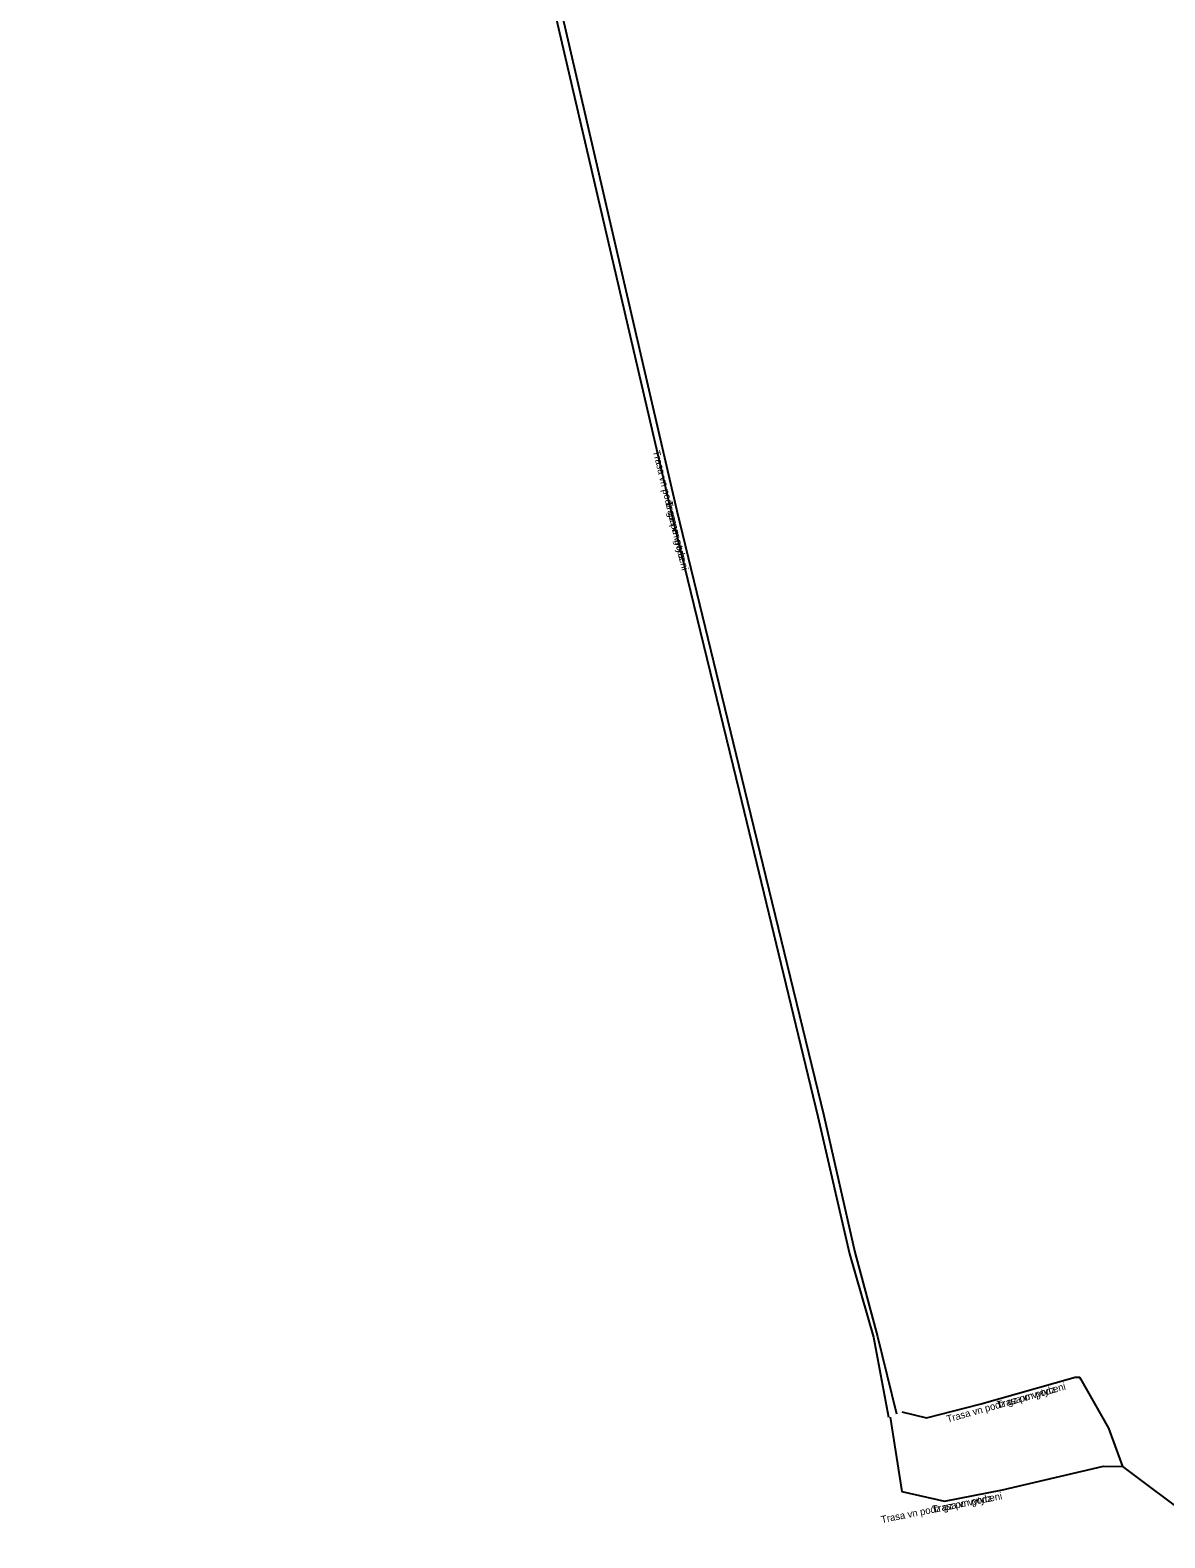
# Model space of a CAD drawing. Extents: x -473162 to -472629, y -1107202 to -1106680.
# Drawn here: x -472952.7 to -472873, y -1107033.1 to -1106927.1 of the extents above; entities that cross this region are included whole.
import ezdxf

# ---------------------------------------------------------------- set-up
doc = ezdxf.new("R2010")
doc.units = 0
doc.layers.add('Popiskový text - Ostatní atributy Trasy', color=7, linetype='Continuous')
doc.layers.add('Spojnice VN', color=7, linetype='Continuous')

msp = doc.modelspace()

# ---------------------------------------------------------------- linework, layer by layer
at = {"layer": 'Spojnice VN'}
for points in [[(-472959.07, -1106901.51), (-472948.71, -1106898.85), (-472943.76, -1106897.66), (-472940.88, -1106899.23), (-472933.49, -1106903.53), (-472927.53, -1106903.31), (-472922.71, -1106902.64), (-472919.35, -1106909.88), (-472918.15, -1106915.27), (-472916.55, -1106922.8), (-472907.68, -1106960.98), (-472902.89, -1106980.6), (-472897.36, -1107003.49), (-472895.13, -1107013.14), (-472893.44, -1107019.01), (-472892.38, -1107024.63)], [(-472959.07, -1106901.51), (-472948.71, -1106898.85), (-472943.76, -1106897.66), (-472940.88, -1106899.23), (-472933.49, -1106903.53), (-472927.53, -1106903.31), (-472922.71, -1106902.64), (-472919.35, -1106909.88), (-472918.15, -1106915.27), (-472916.55, -1106922.8), (-472907.68, -1106960.98), (-472902.89, -1106980.6), (-472897.36, -1107003.49), (-472895.13, -1107013.14), (-472893.44, -1107019.01), (-472892.38, -1107024.63)], [(-472922.47, -1106902.33), (-472919.06, -1106909.81), (-472917.89, -1106915.23), (-472916.11, -1106922.66), (-472907.28, -1106960.88), (-472902.51, -1106980.47), (-472896.93, -1107003.41), (-472894.77, -1107013.03), (-472893.17, -1107018.95), (-472891.83, -1107024.39)], [(-472922.47, -1106902.33), (-472919.06, -1106909.81), (-472917.89, -1106915.23), (-472916.11, -1106922.66), (-472907.28, -1106960.88), (-472902.51, -1106980.47), (-472896.93, -1107003.41), (-472894.77, -1107013.03), (-472893.17, -1107018.95), (-472891.83, -1107024.39)], [(-472875.93, -1107028.1), (-472871, -1107031.82), (-472861.33, -1107033.12), (-472850.8, -1107030.64), (-472845.32, -1107029.36), (-472833.57, -1107026.45), (-472822.85, -1107023.72), (-472815.1, -1107022.25), (-472801.34, -1107019), (-472791.51, -1107016.55), (-472781.55, -1107013.95), (-472772.18, -1107011.27), (-472769.48, -1107010.31), (-472760.41, -1107005.48), (-472750.82, -1106999.47), (-472737.83, -1106992.21), (-472734.32, -1106989.81), (-472728.85, -1106987.34), (-472726.78, -1106986.17), (-472724.29, -1106985.16)], [(-472875.93, -1107028.1), (-472871, -1107031.82), (-472861.33, -1107033.12), (-472850.8, -1107030.64), (-472845.32, -1107029.36), (-472833.57, -1107026.45), (-472822.85, -1107023.72), (-472815.1, -1107022.25), (-472801.34, -1107019), (-472791.51, -1107016.55), (-472781.55, -1107013.95), (-472772.18, -1107011.27), (-472769.48, -1107010.31), (-472760.41, -1107005.48), (-472750.82, -1106999.47), (-472737.83, -1106992.21), (-472734.32, -1106989.81), (-472728.85, -1106987.34), (-472726.78, -1106986.17), (-472724.29, -1106985.16)], [(-472891.45, -1107024.26), (-472889.72, -1107024.68), (-472885.96, -1107023.71), (-472879.26, -1107021.83), (-472878.97, -1107021.83), (-472878.88, -1107021.94), (-472876.93, -1107025.42), (-472875.93, -1107028.1)], [(-472891.45, -1107024.26), (-472889.72, -1107024.68), (-472885.96, -1107023.71), (-472879.26, -1107021.83), (-472878.97, -1107021.83), (-472878.88, -1107021.94), (-472876.93, -1107025.42), (-472875.93, -1107028.1)], [(-472892.27, -1107024.63), (-472891.46, -1107029.86), (-472888.46, -1107030.55), (-472884.38, -1107029.75), (-472877.28, -1107028.08), (-472875.93, -1107028.1)], [(-472892.27, -1107024.63), (-472891.46, -1107029.86), (-472888.46, -1107030.55), (-472884.38, -1107029.75), (-472877.28, -1107028.08), (-472875.93, -1107028.1)]]:
    msp.add_lwpolyline(points, dxfattribs=at)

# ---------------------------------------------------------------- texts
at = {"layer": 'Popiskový text - Ostatní atributy Trasy'}
for s, rotation, p in [('Trasa vn podz gz po vytyceni', 283.6814, (-472908.96, -1106956.69)), ('Trasa vn podz', 283.6814, (-472908.09, -1106960.27)), ('Trasa vn podz gz po vytyceni', 15.6851, (-472888.23, -1107025.02)), ('Trasa vn podz', 15.6851, (-472884.68, -1107024.03)), ('Trasa vn podz gz po vytyceni', 11.2423, (-472892.86, -1107032.09)), ('Trasa vn podz', 11.2423, (-472889.25, -1107031.37))]:
    msp.add_text(s, height=0.5, rotation=rotation, dxfattribs=at).set_placement(p)

doc.saveas('drawing.dxf')
